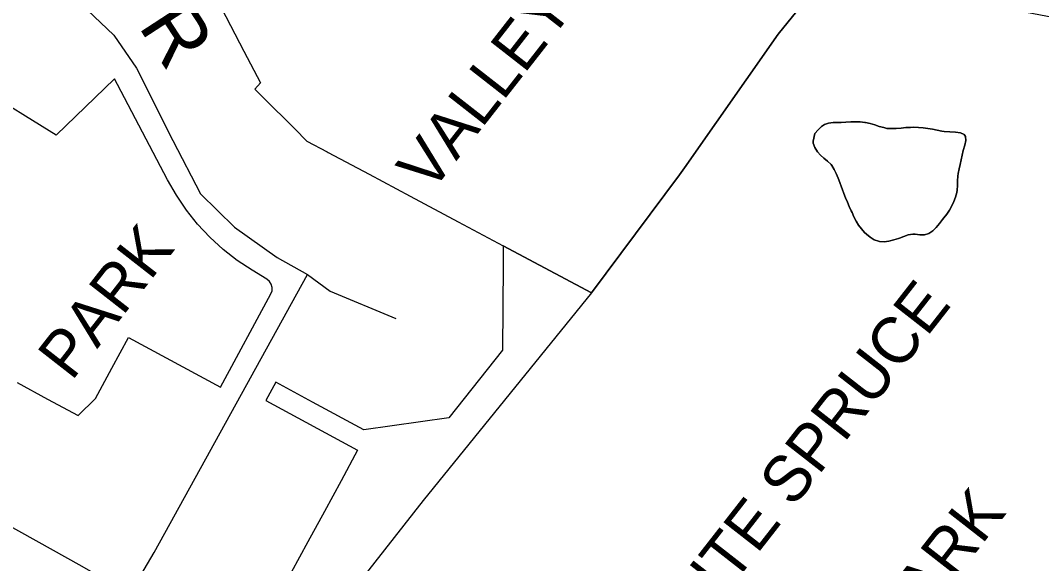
# Model space of a CAD drawing. Extents: x 586326 to 623965, y 4819854 to 4857850.
# Drawn here: x 598101.5 to 598541.6, y 4842551.5 to 4842785.7 of the extents above; entities that cross this region are included whole.
import ezdxf

# ---------------------------------------------------------------- set-up
doc = ezdxf.new("R2010")
doc.units = 0
for name, color, linetype in [('Lots_Concessions', 7, 'Continuous'), ('Minor Rd Lbls', 7, 'Continuous'), ('Minor Rds', 7, 'Continuous'), ('Park Lbls', 7, 'Continuous'), ('Park Outlines', 7, 'Continuous')]:
    doc.layers.add(name, color=color, linetype=linetype)

msp = doc.modelspace()

# ---------------------------------------------------------------- linework, layer by layer
at = {"layer": 'Lots_Concessions'}
for p, q in [((598455.24, 4842813.39), (598428.05, 4842779.68)), ((598428.05, 4842779.68), (598387.76, 4842722.11)), ((598387.76, 4842722.11), (598347.64, 4842668.16)), ((598347.64, 4842668.16), (598275.11, 4842578.64)), ((598275.11, 4842578.64), (598210.1, 4842495.92))]:
    msp.add_line(p, q, dxfattribs=at)
at = {"layer": 'Minor Rds'}
for points in [[(597905.17, 4843005.62), (597946.49, 4842972.01), (597959.43, 4842960.96), (597974.82, 4842940.05), (597989.51, 4842919.05), (598005.3, 4842904.34), (598078.28, 4842825.59), (598097.75, 4842809.9), (598117.75, 4842798.95), (598130.47, 4842790.05), (598141.76, 4842779.32), (598151.53, 4842765.03), (598167.23, 4842733.96), (598179.09, 4842710.98), (598193.78, 4842696.48), (598212.13, 4842683.42), (598225.18, 4842676.11)], [(597829.52, 4842773.58), (597911.01, 4842690.34), (597977.5, 4842649.81), (598062.25, 4842586.98), (598128.01, 4842550.44), (598141.44, 4842542.59), (598153.42, 4842546.55), (598159.16, 4842556.34), (598225.18, 4842676.11)], [(598225.18, 4842676.11), (598235.06, 4842668.91), (598263.27, 4842657.1)]]:
    msp.add_lwpolyline(points, dxfattribs=at)
at = {"layer": 'Park Outlines'}
for points in [[(598188.21, 4842790.92), (598197.86, 4842772.45), (598204.98, 4842758.81), (598202.59, 4842756.01), (598206.03, 4842752.57), (598219.76, 4842738.88), (598224.99, 4842733.66), (598233.73, 4842728.99), (598234.16, 4842728.76), (598251.82, 4842719.33), (598269.49, 4842709.9), (598290.14, 4842698.87), (598309.56, 4842688.5), (598347.64, 4842668.16), (598385.56, 4842719.15), (598387.76, 4842722.11), (598428.05, 4842779.68), (598453.55, 4842811.17)], [(598588.74, 4842778.95), (598523.76, 4842791.29), (598479.69, 4842805.5), (598467.28, 4842809.51), (598461.17, 4842811.48), (598455.24, 4842813.39), (598453.55, 4842811.17), (598428.05, 4842779.68), (598387.76, 4842722.11), (598385.56, 4842719.15), (598347.64, 4842668.16), (598309.56, 4842688.5), (598309.5, 4842680.48), (598309.22, 4842643.55), (598286.18, 4842614.34), (598249.49, 4842609.15), (598227.41, 4842621.13), (598211.59, 4842629.71), (598207.3, 4842621.8), (598246.84, 4842600.35), (598239.7, 4842587.17), (598232.55, 4842573.99), (598225.4, 4842560.81), (598218.25, 4842547.62)], [(598100.07, 4842629.58), (598113.25, 4842622.43), (598126.43, 4842615.28), (598133.84, 4842622.64), (598140.98, 4842635.82), (598148.13, 4842649), (598187.68, 4842627.55), (598209.47, 4842667.73), (598209.95, 4842669.08), (598210.01, 4842670.52), (598209.64, 4842671.91), (598208.87, 4842673.12), (598207.77, 4842674.05), (598207.77, 4842674.05), (598201.41, 4842677.93), (598194.97, 4842682.21), (598188.88, 4842686.97), (598183.18, 4842692.19), (598177.89, 4842697.84), (598173.06, 4842703.88), (598168.72, 4842710.27), (598164.87, 4842716.98), (598143.39, 4842758.11), (598142.12, 4842760.44), (598116.91, 4842736.18), (598103.77, 4842744.34), (598090.62, 4842752.5)]]:
    msp.add_lwpolyline(points, dxfattribs=at)
for points in [[(598443.85, 4842736.96), (598445.26, 4842738.51), (598446.72, 4842739.94), (598447.96, 4842740.81), (598449.81, 4842741.43), (598451.83, 4842741.65), (598453.95, 4842741.65), (598455.23, 4842741.62), (598457.27, 4842741.79), (598459.31, 4842741.91), (598461.35, 4842741.96), (598463.38, 4842741.9), (598465.39, 4842741.71), (598465.74, 4842741.66), (598467.71, 4842741.2), (598469.66, 4842740.61), (598471.61, 4842739.99), (598473.57, 4842739.44), (598474.94, 4842739.14), (598476.95, 4842739.05), (598478.97, 4842739.11), (598481, 4842739.26), (598483.04, 4842739.44), (598485.08, 4842739.58), (598486.53, 4842739.63), (598488.55, 4842739.51), (598490.57, 4842739.31), (598492.58, 4842739.05), (598494.59, 4842738.73), (598496.59, 4842738.36), (598498.59, 4842737.96), (598499.54, 4842737.76), (598502.03, 4842737.69), (598504.46, 4842737.54), (598506.6, 4842737.19), (598508.19, 4842736.46), (598508.85, 4842735.65), (598508.97, 4842733.95), (598508.51, 4842731.87), (598507.83, 4842729.65), (598507.8, 4842729.57), (598507.36, 4842727.59), (598506.89, 4842725.61), (598506.42, 4842723.63), (598505.99, 4842721.64), (598505.62, 4842719.65), (598505.45, 4842718.54), (598505.36, 4842716.49), (598505.3, 4842714.45), (598505.15, 4842712.43), (598504.99, 4842711.44), (598504.5, 4842709.47), (598503.8, 4842707.55), (598502.93, 4842705.69), (598501.9, 4842703.9), (598500.73, 4842702.2), (598499.43, 4842700.58), (598498.83, 4842699.9), (598497.57, 4842698.11), (598496.18, 4842696.42), (598494.65, 4842694.96), (598492.99, 4842693.86), (598491.17, 4842693.23), (598491.12, 4842693.22), (598489.15, 4842693.29), (598487.09, 4842693.55), (598486.1, 4842693.59), (598484.15, 4842693.17), (598482.22, 4842692.49), (598480.29, 4842691.79), (598479.88, 4842691.66), (598477.84, 4842691.04), (598475.79, 4842690.53), (598473.76, 4842690.26), (598471.8, 4842690.36), (598471.33, 4842690.46), (598469.46, 4842691.13), (598467.7, 4842692.19), (598466.08, 4842693.53), (598465.3, 4842694.31), (598463.93, 4842695.76), (598462.74, 4842697.38), (598461.69, 4842699.14), (598460.74, 4842700.99), (598459.88, 4842702.88), (598459.55, 4842703.63), (598458.69, 4842705.46), (598457.9, 4842707.33), (598457.15, 4842709.22), (598456.41, 4842711.12), (598455.67, 4842713.01), (598455.33, 4842713.85), (598454.62, 4842715.78), (598453.9, 4842717.72), (598453.11, 4842719.61), (598452.22, 4842721.42), (598451.17, 4842723.13), (598450.86, 4842723.56), (598449.37, 4842724.95), (598447.78, 4842726.26), (598446.25, 4842727.61), (598445, 4842729.08), (598443.84, 4842730.85), (598443.16, 4842732.77), (598443.08, 4842733.62)], [(598443.85, 4842736.96), (598443.08, 4842733.62), (598443.16, 4842732.77), (598443.84, 4842730.85), (598445, 4842729.08), (598446.25, 4842727.61), (598447.78, 4842726.26), (598449.37, 4842724.95), (598450.86, 4842723.56), (598451.17, 4842723.13), (598452.22, 4842721.42), (598453.11, 4842719.61), (598453.9, 4842717.72), (598454.62, 4842715.78), (598455.33, 4842713.85), (598455.67, 4842713.01), (598456.41, 4842711.12), (598457.15, 4842709.22), (598457.9, 4842707.33), (598458.69, 4842705.46), (598459.55, 4842703.63), (598459.88, 4842702.88), (598460.74, 4842700.99), (598461.69, 4842699.14), (598462.74, 4842697.38), (598463.93, 4842695.76), (598465.3, 4842694.31), (598466.08, 4842693.53), (598467.7, 4842692.19), (598469.46, 4842691.13), (598471.33, 4842690.46), (598471.8, 4842690.36), (598473.76, 4842690.26), (598475.79, 4842690.53), (598477.84, 4842691.04), (598479.88, 4842691.66), (598480.29, 4842691.79), (598482.22, 4842692.49), (598484.15, 4842693.17), (598486.1, 4842693.59), (598487.09, 4842693.55), (598489.15, 4842693.29), (598491.12, 4842693.22), (598491.17, 4842693.23), (598492.99, 4842693.86), (598494.65, 4842694.96), (598496.18, 4842696.42), (598497.57, 4842698.11), (598498.83, 4842699.9), (598499.43, 4842700.58), (598500.73, 4842702.2), (598501.9, 4842703.9), (598502.93, 4842705.69), (598503.8, 4842707.55), (598504.5, 4842709.47), (598504.99, 4842711.44), (598505.15, 4842712.43), (598505.3, 4842714.45), (598505.36, 4842716.49), (598505.45, 4842718.54), (598505.62, 4842719.65), (598505.99, 4842721.64), (598506.42, 4842723.63), (598506.89, 4842725.61), (598507.36, 4842727.59), (598507.8, 4842729.57), (598507.83, 4842729.65), (598508.51, 4842731.87), (598508.97, 4842733.95), (598508.85, 4842735.65), (598508.19, 4842736.46), (598506.6, 4842737.19), (598504.46, 4842737.54), (598502.03, 4842737.69), (598499.54, 4842737.76), (598498.59, 4842737.96), (598496.59, 4842738.36), (598494.59, 4842738.73), (598492.58, 4842739.05), (598490.57, 4842739.31), (598488.55, 4842739.51), (598486.53, 4842739.63), (598485.08, 4842739.58), (598483.04, 4842739.44), (598481, 4842739.26), (598478.97, 4842739.11), (598476.95, 4842739.05), (598474.94, 4842739.14), (598473.57, 4842739.44), (598471.61, 4842739.99), (598469.66, 4842740.61), (598467.71, 4842741.2), (598465.74, 4842741.66), (598465.39, 4842741.71), (598463.38, 4842741.9), (598461.35, 4842741.96), (598459.31, 4842741.91), (598457.27, 4842741.79), (598455.23, 4842741.62), (598453.95, 4842741.65), (598451.83, 4842741.65), (598449.81, 4842741.43), (598447.96, 4842740.81), (598446.72, 4842739.94), (598445.26, 4842738.51)]]:
    msp.add_lwpolyline(points, close=True, dxfattribs=at)

# ---------------------------------------------------------------- texts
at = {"layer": 'Minor Rd Lbls'}
msp.add_text('R', height=25, rotation=303.0608, dxfattribs=at).set_placement((598152.04, 4842783.27))
at = {"layer": 'Park Lbls'}
for s, p in [('VALLEY', (598278.34, 4842710.8)), ('PARK', (598123.58, 4842629.8)), ('WHITE SPRUCE', (598376.86, 4842501.46)), ('PARK', (598481.95, 4842516.04))]:
    msp.add_text(s, height=19.992, rotation=52, dxfattribs=at).set_placement(p)

doc.saveas('drawing.dxf')
